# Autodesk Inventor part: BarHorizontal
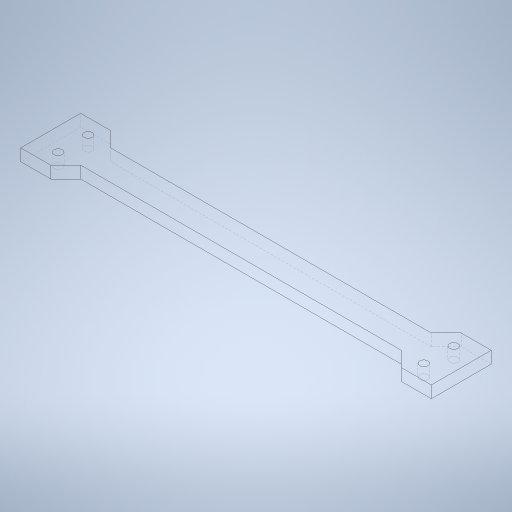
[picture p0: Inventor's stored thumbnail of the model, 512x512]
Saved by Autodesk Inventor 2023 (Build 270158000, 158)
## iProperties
Created: 2023-10
Part Number: BarHorizontal
Material: Aluminum 7075
Document SubType Name: Modeling
Designer: tornqvih
Density: 2.81 g/cm^3
Appearance: Satin - Brushed Heavy
Mass: 142.466 g
Surface Area: 186.608 cm^2
Volume: 50.6996 cm^3
Author: tornqvih
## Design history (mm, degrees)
sketch "Sketch1"
  geometry: L1 (107, -10)-(-107, -10); L2 (-107, -10)-(-117, -20); L3 (-117, -20)-(-137, -20); L4 (-137, -20)-(-137, 20); L5 (-137, 20)-(-117, 20); L6 (-117, 20)-(-107, 10); L7 (-107, 10)-(107, 10); L8 (107, 10)-(117, 20); L9 (117, 20)-(137, 20); L10 (137, 20)-(137, -20); L11 (137, -20)-(117, -20); L12 (117, -20)-(107, -10); L13 (191.8, 0)-(-191.8, 0) reference; L14 (0, -28)-(0, 28) reference
  constraints: 24 end point, 9 symmetric about line, 1 horizontal
  dimensions: "d9" = 40 distance of L9.end L10.end; "d11" = 20 distance of L10.end L11.end; "d29" = 45 deg angle of L12 L1; "d30" = 234 distance of L2.end L11.end; "d32" = 20 distance between parallel lines of L7 L1
extrude "Extrusion2" new body sketch "Sketch1" distance "d13" = 8; taper "d14" = 0 deg
sketch "Sketch3"
  geometry: L1 (-191.8, 0)-(191.8, 0) reference; L2 (0, 28)-(0, -28) reference; L3 (-117, 20)-(-137, 20) reference; L4 (-137, 20)-(-137, -20) reference; 5 further points
  constraints: 3 symmetric about line
  dimensions: "d33" = 5 horizontal distance of L3.start point (-122, 10); "d34" = 10 distance from line of L1 point (-122, 10)
hole "Hole1" sketch "Sketch3" at (-122, 10), (-122, -10), (122, 10), (122, -10) diameter "d15" = 5.5; stored, may be unused: countersink angle "d19" = 90 deg, drill point angle "d21" = 118 deg; dims "d16" = 6, "d17" = 4, "d18" = 2, "d20" = 8
body "Solid2"
